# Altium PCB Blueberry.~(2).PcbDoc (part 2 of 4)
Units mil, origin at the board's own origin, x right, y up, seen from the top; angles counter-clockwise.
Board outline 2559.06 x 2204.72 mil, 6 copper layers (Top Layer, Mid-Layer 1, Mid-Layer 2, Mid-Layer 3, Mid-Layer 4, Bottom Layer); 211 components, 214 nets, 1171 pads, 598 vias.
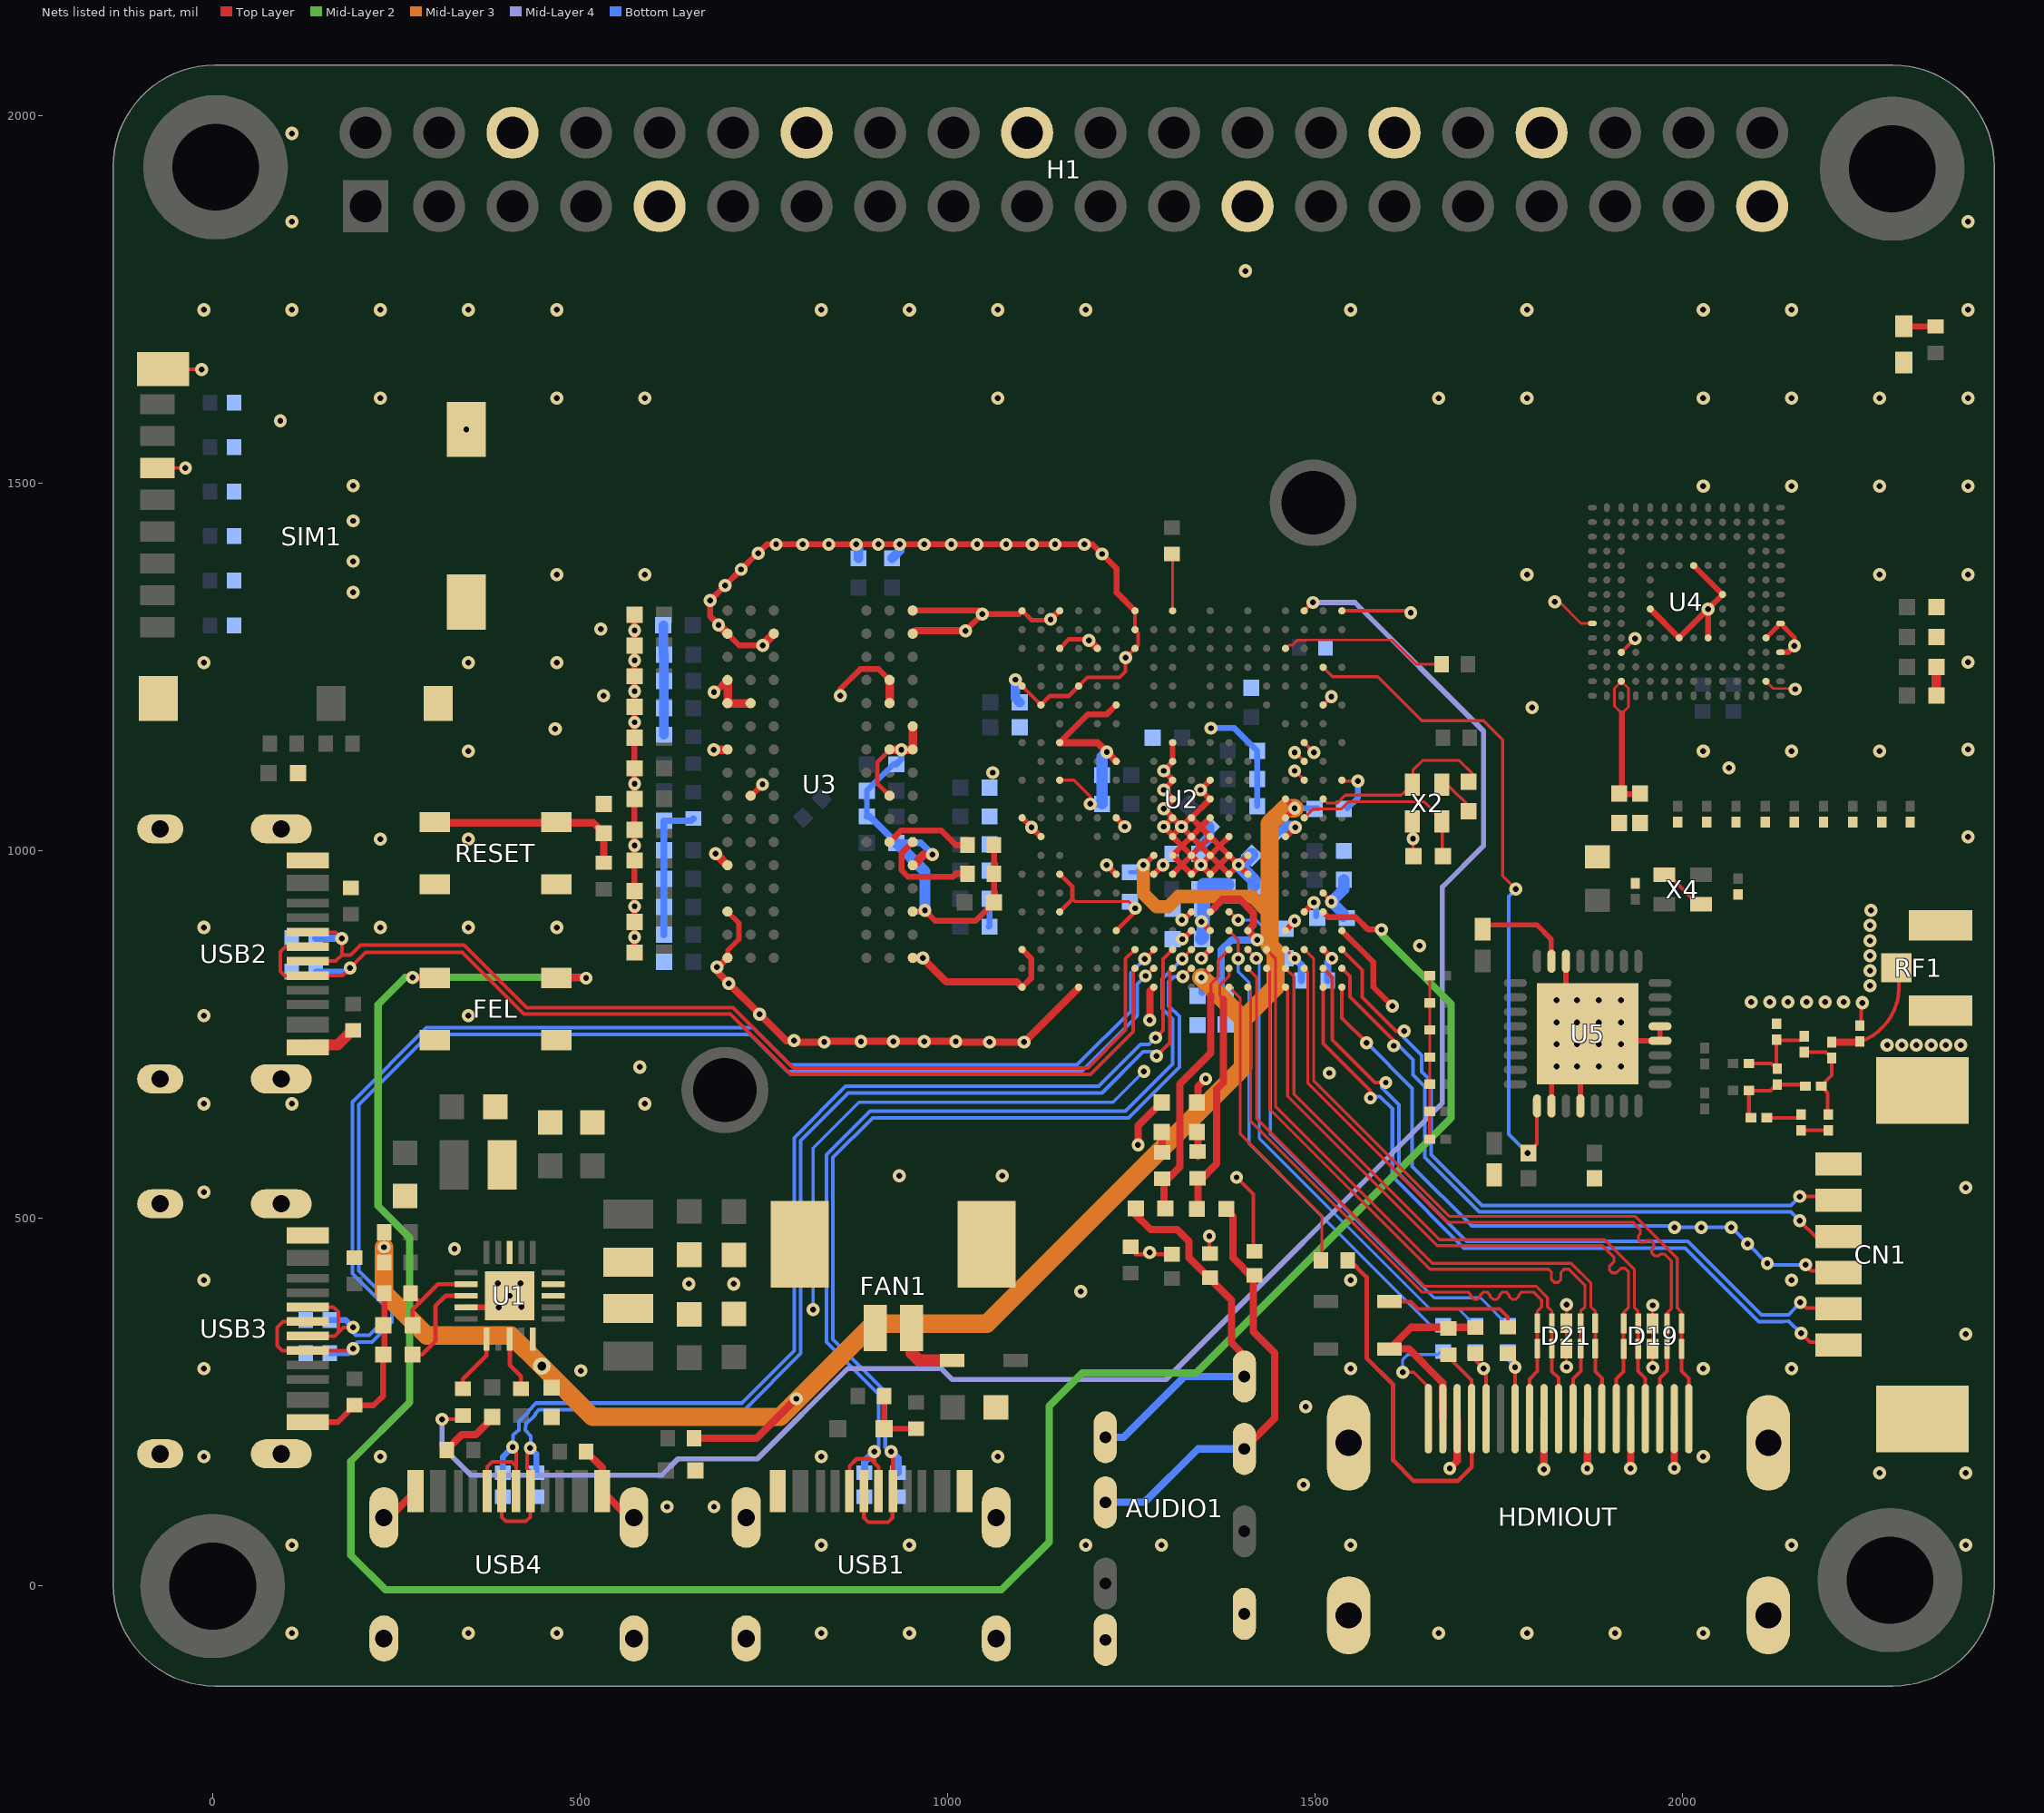
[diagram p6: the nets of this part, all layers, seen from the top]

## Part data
AUDIO1: Current Rating (Max)=500mA, JLCPCB Part Class="Extended Part", LCSC Part Name=3.5mm耳机座, Manufacturer=韩国韩荣, Voltage Rating (Max)=30V
C66 C67 C68 C69 C70 C71 C104 C105 C106 C107 C108 C117 C120: JLCPCB Part Class="Extended Part", LCSC Part Name="100nF ±10% 16V", Manufacturer=SAMSUNG(三星), Temperature Coefficient=X5R, Tolerance=±10%, Voltage Rated=16V
C87: JLCPCB Part Class="Extended Part", LCSC Part Name="100nF ±10% 25V", Manufacturer=PSA(信昌电陶), Temperature Coefficient=X7R, Tolerance=±10%, Voltage Rated=25V
C102: JLCPCB Part Class="Extended Part", LCSC Part Name="100pF ±5% 50V", Manufacturer=FH(风华), Temperature Coefficient=C0G, Tolerance=±5%, Voltage Rated=50V
C109 C123: JLCPCB Part Class="Extended Part", LCSC Part Name="7pF 25V ±0.25pF", Manufacturer=FH(风华), Temperature Coefficient=C0G, Voltage Rated=25V
C110 C113 C114 C115: JLCPCB Part Class=扩展库, LCSC Part Name="1pF 50V ±0.05pF", Manufacturer=muRata(村田), Temperature Coefficient=C0G, Voltage Rated=50V
C112 C119: JLCPCB Part Class=扩展库, LCSC Part Name="1.2pF 50V ±0.1pF", Manufacturer=FH(风华), Temperature Coefficient=C0G, Voltage Rated=50V
C116 C124: JLCPCB Part Class="Extended Part", LCSC Part Name="4.7uF ±20% 6.3V", Manufacturer=muRata(村田), Temperature Coefficient=X5R, Tolerance=±20%, Voltage Rated=6.3V
C118: JLCPCB Part Class=基础库, LCSC Part Name="10uF ±20% 6.3V", Manufacturer=SAMSUNG(三星), Temperature Coefficient=X5R, Tolerance=±20%, Voltage Rated=6.3V
C121 C122: JLCPCB Part Class="Extended Part", LCSC Part Name="22pF ±5% 50V", Manufacturer=YAGEO(国巨), Temperature Coefficient=NP0, Tolerance=±5%, Voltage Rated=50V
CN1: JLCPCB Part Class="Extended Part", Manufacturer=MOLEX
D1 D22 D23: Average Rectified Current (Io)=1A, Forward Voltage (Vf@If)=600mV@1A, JLCPCB Part Class="Extended Part", LCSC Part Name="40V 1A 600mV@1A", Manufacturer=CJ（江苏长电/长晶）, Reverse Voltage (Vr)=40V
D2 D3 D4 D5 D6 D7 D8 D9 D10 D11 D12 D13 D14 D15 D16 D17 D18: Current - Peak Pulse (10/1000μs)=-, JLCPCB Part Class="Extended Part", Manufacturer=BORN伯恩半导体, Voltage - Clamping (Max) @ Ipp=50V, Voltage - Reverse Standoff (Typ)=5V
D19 D21: JLCPCB Part Class="Extended Part", Manufacturer=SEMTECH
D20: JLCPCB Part Class="Extended Part"
FAN1: Current Rating (Max)=-, JLCPCB Part Class="Extended Part", LCSC Part Name=线至板连接器,2触点,针座,1.25mm,贴装,1排, Manufacturer=MOLEX
FEL RESET: Contact Current=50mA, JLCPCB Part Class="Extended Part", LCSC Part Name="4.2*3.2*2.5mm 立贴 轻触开关", Manufacturer=C&K, Operating Force=160gf, Operating Temperature=-40℃~+85℃, Voltage Rating (DC)=16V
H1: Color=黑色, Current Rating (Max)=-, JLCPCB Part Class="Extended Part", LCSC Part Name="2.54mm 2x20P 直插", Manufacturer=Ckmtw(灿科盟), Operating Temperature Range=-40℃~+105℃
HDMIOUT: Current Rating (Max)=500mA, JLCPCB Part Class="Extended Part", LCSC Part Name="HDMI 母 P数:19", Manufacturer=SOFNG(硕方), Operating Temperature Range=-25~+75
L1 L2 L3: DC Resistance (DCR)=264mΩ, JLCPCB On Sale=1, JLCPCB Part Class="Extended Part", LCSC Part Name="2.2uH ±20% 1.1A 264mΩ", Manufacturer=CENKER(岑科), Manufacturer Part=CKCS201610-2.2uH/M, Rated Current=1.1A, Tolerance=±20%
L4 L5: DC Resistance (DCR)=700mΩ, Frequency - Self Resonant=3.2GHz, JLCPCB Part Class=扩展库, LCSC Part Name="10nH ±3%", Manufacturer=muRata(村田), Q @ Freq=14@500MHz, Rated Current=250mA, Ratings=-, Tolerance=±3%
L6 L7 L8: DC Resistance (DCR)=200mΩ, Frequency - Self Resonant=500MHz, JLCPCB Part Class=扩展库, LCSC Part Name="2.7nH ±0.1nH", Manufacturer=Sunlord(顺络), Q @ Freq=13@500MHz, Rated Current=500mA, Ratings=-
L9: DC Resistance (DCR)=-, JLCPCB Part Class=扩展库, LCSC Part Name="4.7uH ±20%", Manufacturer=TDK, Tolerance=±20%
LED1: Color Temperature=6000K~7000K, Emitted Color=红灯, Forward Current=25mA, JLCPCB Part Class="Extended Part", LCSC Part Name="红灯 正贴 色温6000K~7000K", Lens Color=无色透明, Manufacturer=XINGLIGHT(成兴光), Operating Temperature=-30℃~+85℃, Power Dissipation=55mW
R28: JLCPCB Part Class="Extended Part", LCSC Part Name="10kΩ ±0.5%", Manufacturer="EVER OHMS(天二科技)", Operating Temperature Range=-55~+155, Overload Voltage (Max)=25V, Power(Watts)=63mW, Temperature Coefficient=±25ppm/, Tolerance=±0.5%
R53: JLCPCB Part Class="Basic Part", LCSC Part Name="1MΩ ±1% 100mW", Manufacturer=UNI-ROYAL(厚声), Operating Temperature Range=-55℃~+155℃, Overload Voltage (Max)=75V, Power(Watts)=100mW, Temperature Coefficient=±100ppm/℃, Tolerance=±1%
R54: JLCPCB Part Class="Extended Part", LCSC Part Name="100kΩ ±1% 62.5mW", Manufacturer=YAGEO(国巨), Operating Temperature Range=-55℃~+155℃, Overload Voltage (Max)=50V, Power(Watts)=62.5mW, Temperature Coefficient=±100ppm/℃, Tolerance=±1%
R56: JLCPCB Part Class="Extended Part", LCSC Part Name="10kΩ ±1% 62.5mW", Manufacturer=YAGEO(国巨), Operating Temperature Range=-55℃~+155℃, Overload Voltage (Max)=50V, Power(Watts)=62.5mW, Temperature Coefficient=±100ppm/℃, Tolerance=±1%
RF1: Frequency-Max=6GHz, JLCPCB Part Class=ExtendedPart, LCSC Part Name=IPEX内针IPEX内针天线座IPEX-1IPEX11代, Manufacturer=BATWIRELESS(蝙蝠无线), Operating Temperature Range=-
SIM1: JLCPCB Part Class="Extended Part", LCSC Part Name="拔插式 MicroSD卡(TF卡) 卡座", Manufacturer=MOLEX, Operating Temperature Range=-
U3: JLCPCB Part Class="Extended Part", Manufacturer=HYNIX(海力士)
U4: Manufacturer=Kingston(金士顿), Manufacturer Part=EMMC04G-M627-A01
U5: JLCPCB Part Class=扩展库, Manufacturer=REALTEK(瑞昱)
USB1 USB2 USB3 USB4: JLCPCB Part Class="Extended Part", Manufacturer=XUNPU
X2 X4: library part SX32Y024000BC1T, Frequency Stability=-, JLCPCB Part Class="Extended Part", LCSC Part Name="3225 24M 12PF  10ppm  -20 -75", Manufacturer=TKD(泰晶)

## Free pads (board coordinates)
  round 196.85 hole 118.11: 1(0,0) 1(4,1930) 1(2282,8) 1(2285,1928)
  round 118.11 hole 86.61: 1(696.94,674.81) 1(1497.12,1473.59)

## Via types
v1: diameter 17.7, hole 7.9, Top Layer to Bottom Layer, 439 vias
v2: diameter 18, hole 8, Top Layer to Bottom Layer, 138 vias
v3: diameter 24, hole 15, Top Layer to Bottom Layer, 19 vias
v4: diameter 24, hole 12, Top Layer to Bottom Layer, 2 vias

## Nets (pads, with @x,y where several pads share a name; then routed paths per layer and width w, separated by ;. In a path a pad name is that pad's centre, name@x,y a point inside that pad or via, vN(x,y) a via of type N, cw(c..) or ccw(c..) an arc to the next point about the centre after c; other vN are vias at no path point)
1V8: C1.2 C14.2 C15.2 C16.2 C98.1 R2.1 R3.1 R49.2 U1.15 U2.D11 U2.D12 U2.F18 U2.H17 U2.H20 U2.L14 | length 2795.3
  Top Layer w8: R3.1@233.44,440.28 233,440.72 v1(233,461) 233,480.84 R2.1@233.44,481.28 ; v1(1266,981) 1267.47,981 U2.L14@1280.38,993.91 ; v1(1345,828) 1345,828.21 U2.H20@1357.16,840.37 ; U2.D12@1459.52,1045.09 1472,1057.57 v1(1472,1058) 1472,1058.19 U2.D11@1459.52,1070.68
  Top Layer w10: R49.2@655,201 740,201 v1(793.88,254.88) ; U2.H17@1357.16,917.14 1374.02,934 1398,934 1416,916 1416,899.21 U2.F18@1408.34,891.55 1420.88,879 v1(1421,879)
  Mid-Layer 3 w18: v1(1266,981) 1266,942 1284,924 1300,924 1314,938 1414.47,938 1438,914.47
  Mid-Layer 3 w25: v1(233,461) 233,399 291,341 406,341 v4(447.72,299.28) 517,230 772,230 899,357 1053.14,357 1402,705.86 1402,771 ; v1(1345,828) 1402,771 ; v1(1472,1058) 1459,1058 1438,1037 1438,914.47 1438,871.14 1446,863.14 1446,815 1402,771
  Bottom Layer w5: C16.2@1248,971.01 1256.01,971.01 v1(1266,981)
  Bottom Layer w8: v1(1472,1058) C98.1@1504.01,1058
  Bottom Layer w10: v1(1345,828) 1346,827 C15.2@1346,808.01 ; C14.2@1378,804.01 1372,810.01 1372,865 1386,879 v1(1421,879)
AGND: C92.1 C93.1 R31.1 R32.2 U2.H18 | length 129.9
  Top Layer w8: v1(1345,904) 1357.16,891.84 U2.H18@1357.16,891.55
  Bottom Layer w8: C92.1@1345,880.99 C92.1@1346.99,879
  Bottom Layer w18: C92.1@1345,880.99 1346.99,882.99 C93.1@1348.21,919 ; C93.1@1348.21,916.09 C93.1@1348.21,919 ; R32.2@1381,954 1348.21,954 C93.1@1348.21,919
ANT: C115.2 L8.1 RF1.1 | length 164.1
  Top Layer w5: C115.2@2240.43,740.17 ccw(c2215.29,814.92) RF1.1@2289.71,841
  Top Layer w10: L8.1@2202.65,739.85 2240.11,739.85 C115.2@2240.43,740.17 ; C115.2@2240,740 ccw(c2209.51,817.73) C115.2@2240.43,740.17 ; C115.2@2241,740.74 C115.2@2240.43,740.17
AP_REG_ON: U2.C9 | length 18.1
  Top Layer w4.5: v1(1472,1134) 1472.96,1134 U2.C9@1485.11,1121.86
BT_RSTN: U2.C10 | length 18.4
  Top Layer w4: v1(1472,1109) 1472.37,1109 U2.C10@1485.11,1096.27
CS: R54.1 U2.B4 U5.25 | length 938.8
  Top Layer w4: U2.B4@1510.7,1249.81 1523.5,1237 1585,1237 1645,1177 1729,1177 1755,1151 1755,966 v1(1773,948)
  Top Layer w5: v1(1789,589) 1801.76,601.76 U5.25@1801.76,653.11
  Bottom Layer w5: v1(1773,948) 1763.25,938.25 1763.25,614.75 v1(1789,589)
D0_N: D9.1 U2.J19 USB1.A7 USB1.B7 | length 1300.2
  Top Layer w5: v1(1319,853) 1331.57,865.57 U2.J19@1331.57,865.96
  Top Layer w5.4: USB1.B7@866.5,129.3 866.5,163.5 876,173 895,173 900,168 ; v1(900,183) 900,168 ; USB1.A7@905.8,129.3 906,129.5 906,162 900,168
  Bottom Layer w5: v1(900,183) 906,189 906,261 835,332 835,586.73 894.27,646 1242,646 1306,710 1306,771.27 1291.64,785.64 1291.64,825.64 v1(1319,853)
  Bottom Layer w10: D9.1@886.86,154.37 886.86,169.86 v1(900,183)
D0_P: D11.1 U2.J20 USB1.A6 USB1.B6 | length 1319.9
  Top Layer w5: v1(923,183) 925.5,180.5 USB1.B6@925.5,129.3 ; v1(1320,829) 1320.2,829 U2.J20@1331.57,840.37
  Top Layer w5.4: USB1.A6@886.2,129.3 886.2,92.8 892,87 919,87 925,93 925,128.8 USB1.B6@925.5,129.3
  Bottom Layer w5: v1(923,183) 921,183 915,189 915,264.73 844,335.73 844,583 898,637 1246,637 1315,706 1315,775 1300.64,789.36 1300.64,821.91 1307.19,828.47 v1(1320,829)
  Bottom Layer w10: v1(923,183) 932.23,173.77 D11.1@932.23,154.37
D1_N: D13.1 U2.M19 USB2.A7 USB2.B7 | length 1434.8
  Top Layer w5: USB2.A7@129.3,850.2 167.32,850.2 175.76,858.64 ; USB2.B7@129.3,889.5 167.32,889.5 v1(175.76,881.06) 175.76,858.64 ; U2.M19@1254.79,865.96 1242,853.17 1242,756.73 1190.27,705 790,705 708,787 427,787 342,872 201,872 187.64,858.64 175.76,858.64
  Bottom Layer w10: D13.1@140.39,881.47 175.35,881.47 v1(175.76,881.06)
D1_P: D14.1 U2.M20 USB2.A6 USB2.B6 | length 1471.8
  Top Layer w5: USB2.A6@129.3,869.8 98.8,869.8 92,863 92,836 98,830 128.8,830 USB2.B6@129.3,830.5 176.5,830.5 v1(187,841) 208,862 339.27,862 423.27,778 704.27,778 786.27,696 1194,696 1252,754 1252,837.58 U2.M20@1254.79,840.37
  Bottom Layer w8: D14.1@140.39,836.1 182.1,836.1 v1(187,841)
D2_N: D17.1 U2.L19 USB3.A7 USB3.B7 | length 1799.8
  Top Layer w5: USB3.A7@129.3,340.2 129.5,340 166,340 171,345 ; USB3.B7@129.3,379.5 164.5,379.5 171,373 171,345 ; v1(191,352) 178,352 171,345 ; v1(1268,853) 1280.38,865.38 U2.L19@1280.38,865.96
  Bottom Layer w5: v1(191,352) 191,344.75 194.75,341 213,341 234.64,362.64 234.64,380.64 190,425.27 190,658.73 290.91,759.64 735.36,759.64 786,709 1176,709 1249,782 1249,834 v1(1268,853)
  Bottom Layer w8: D17.1@159.39,361.99 181.01,361.99 v1(191,352)
D2_P: D18.1 U2.L20 USB3.A6 USB3.B6 | length 1819.5
  Top Layer w5: USB3.A6@129.3,359.8 95.8,359.8 88,352 88,327 94.5,320.5 USB3.B6@129.3,320.5 188.5,320.5 v1(191,323) ; v1(1269,830) 1279.37,840.37 U2.L20@1280.38,840.37
  Bottom Layer w5: v1(191,323) 191,325.75 197.25,332 216.73,332 243.64,358.91 243.64,384.36 199,429 199,655 294.64,750.64 731.64,750.64 782.27,700 1182,700 1258,776 1258,819 v1(1269,830)
  Bottom Layer w8: D18.1@159.39,316.62 184.62,316.62 v1(191,323)
D3_N: D15.1 U2.K19 USB4.A7 USB4.B7 | length 1600.8
  Top Layer w5: USB4.B7@373.5,129.3 373.5,162.5 380,169 407,169 413,163 ; v1(408,189) 413,184 413,163 ; USB4.A7@412.8,129.3 413,129.5 413,163 ; v1(1283,746) 1293,756 1293,852.99 U2.K19@1305.97,865.96
  Bottom Layer w5: v1(408,189) 408.68,205.34 416.5,212.53 416.81,220.02 416.81,223.75 429.7,236.64 429.7,238.42 440.27,249 720,249 791,320 791,609.73 861.27,680 1205.27,680 1262.27,737 1274,737 v1(1283,746)
  Bottom Layer w8: D15.1@394.86,154.37 394.86,159.89 394.86,175.86 v1(408,189)
D3_P: D16.1 U2.K20 USB4.A6 USB4.B6 | length 1618.7
  Top Layer w5: USB4.A6@393.2,129.3 393.2,93.8 399,88 426,88 432,94 432,128.8 USB4.B6@432.5,129.3 432.5,155.5 428,160 428,184 v1(432,188) ; v1(1284,721) 1302,739 1302,836.4 U2.K20@1305.97,840.37
  Bottom Layer w5: v1(432,188) 432.68,204.34 425.49,212.15 425.81,219.83 425.81,220.02 438.7,232.91 438.7,234.7 444,240 723.73,240 800,316.27 800,606 865,671 1210,671 1266,727 1278,727 v1(1284,721)
  Bottom Layer w8: v1(432,188) 440.23,179.77 440.23,159.89 D16.1@440.23,154.37
EPHY_RTX: R26.1 U2.B19 | length 49.6
  Top Layer w8: U2.B19@1510.7,865.96 v1(1522.65,854) v1@1523,854
  Bottom Layer w10: R26.1@1517,824 1517,848.34 v1(1522.65,854)
EPHY_RX_N: CN1.6 U2.B21 | length 1008.8
  Top Layer w5: U2.B21@1510.7,814.77 1510.7,738.3 1575,674 v1(1575,664) ; v1(2161,344) 2173,332 2207.88,332 CN1.6@2211.88,328
  Bottom Layer w5: v1(1575,664) 1577.07,666.07 1587.93,666.07 1605,649 1605,557.27 1702.27,460 2003.27,460 2103.34,359.93 2136.5,359.93 2144.11,360.11 v1(2161,344)
EPHY_RX_P: CN1.5 U2.B20 | length 1027.6
  Top Layer w5: U2.B20@1510.7,840.37 1523,828.06 1523,743 1581,685 v1(1596,685) ; v1(2160,386) 2168,378 2215.1,378 CN1.5@2215.9,377.2
  Bottom Layer w5: v1(1596,685) 1590.75,679.75 1590.75,678.25 1614,655 1614,561 1706,469 2007,469 2107.07,368.93 2136.39,368.93 2143.89,369.11 v1(2160,386)
EPHY_TX_N: CN1.3 U2.A20 | length 915.9
  Top Layer w5: U2.A20@1536.29,840.37 1547.29,829.37 1547.29,801.71 1607,742 v1(1607,735) ; v1(2159,497) 2181,475 2211.28,475 CN1.3@2211.88,475.6
  Bottom Layer w5: v1(1607,735) 1614,735 1633,716 1633,695.31 1649,679.31 1649,583.27 1723.27,509 2147,509 v1(2159,497)
EPHY_TX_P: CN1.2 U2.A19 | length 930.8
  Top Layer w5: U2.A19@1536.29,865.96 1564,838.24 1564,801 1610,755 v1(1621,755) ; v1(2159,530) 2213.1,530 2215.9,527.2 CN1.2@2215.9,524.8
  Bottom Layer w5: v1(1621,755) 1621,746 1645,722 1645,700 1658,687 1658,587 1727,518 2147,518 v1(2159,530)
FEL: FEL.1 FEL.2 U2.B17 | length 3453.7
  Top Layer w8: U2.B17@1510.7,917.14 1517.83,910 1555,910 1572,893 v1(1590,893)
  Top Layer w10: v1(272,828) 306.6,828 305.9,827.3 FEL.1@302.32,827.32 ; FEL.2@467.68,827.32 507.7,827.3 v1(508,827)
  Mid-Layer 2 w10: v1(508,827) 507,828 v1(272,828) 262,828 225,791 225,517 268,474 268,250 188,170 188,42 235,-5 1073,-5 1138,60 1138,245 1183,290 1338,290 1685,637 1685,792 1590,887 v1(1590,893)
GND: AUDIO1.1 AUDIO1.8 C1.1 C2.2 C3.1 C4.2 C5.1 C6.2 C7.2 C8.2 C9.2 C10.2 C11.2 C12.1 C13.2 C14.1 C15.1 C16.1 C17.1 C18.1 C19.1 C20.1 C21.1 C22.1 C23.1 C24.1 C25.1 C26.1 C27.1 C28.1 C29.1 C30.1 C31.1 C32.1 C33.1 C34.1 C35.1 C36.1 C37.1 C38.1 C39.1 C40.1 C41.1 C42.1 C43.1 C44.1 C45.1 C46.1 C47.1 C48.1 C49.1 C50.1 C51.1 C52.1 C53.1 C54.1 C55.1 C56.1 C57.1 C58.1 C59.1 C60.1 C61.1 C62.1 C63.1 C64.1 C65.1 C66.2 C67.2 C68.1 C69.1 C70.1 C71.1 C75.1 C76.1 C77.1 C81.1 C82.1 C83.1 C87.2 C88.1 C90.1 C94.2 C95.1 C96.1 C97.2 C98.2 C99.2 C100.1 C102.1 C104.2 C105.2 C106.2 C107.1 C108.2 C114.1 C115.1 C116.1 C117.1 C118.1 C119.2 C120.2 C121.2 C122.2 C124.2 CN1.1 CN1.4 CN1.7 CN1.8 D2.1 D3.1 D4.1 D5.1 D6.1 D7.1 D8.1 D9.2 D10.1 D11.2 D12.1 D13.2 D14.2 D15.2 D16.2 D17.2 D18.2 D19.3 D19.8 D21.3 D21.8 FAN1.2 FAN1.3 FAN1.4 FEL.3 FEL.4 H1.6 H1.9 H1.14 H1.20 H1.25 H1.30 H1.34 H1.39 HDMIOUT.2 HDMIOUT.5 HDMIOUT.8 HDMIOUT.11 HDMIOUT.17 HDMIOUT.20 HDMIOUT.21 HDMIOUT.22 HDMIOUT.23 L6.1 LED1.2 R1.1 R6.2 R8.1 R9.1 R11.1 R26.2 R30.1 R32.1 R35.1 R36.2 R40.1 R43.2 R44.1 R46.2 R52.2 R53.1 R56.2 RESET.3 RESET.4 RF1.2 RF1.3 SIM1.6 SIM1.9 SIM1.10 SIM1.12 SIM1.13 SIM1.14 U1.9 U1.21 U2.A1 U2.A10 U2.A18 U2.A21 U2.B6 U2.B16 U2.D19 U2.F14 U2.F15 U2.G13 U2.G14 U2.G15 U2.H10 U2.H11 U2.H12 U2.H13 U2.H14 U2.H15 U2.H19 U2.J12 U2.J13 U2.J14 U2.J15 U2.K8 U2.K9 U2.K10 U2.K11 U2.K12 U2.K13 U2.K14 U2.K15 U2.L21 U2.M1 U2.M2 U2.M3 U2.N6 U2.N9 U2.N12 U2.N15 U2.N18 U2.P3 U2.R5 U2.R21 U2.T1 U2.T3 U2.T8 U2.T10 U2.T15 U2.T17 U2.U6 U2.U13 U2.V1 U2.V5 U2.V12 U2.V19 U2.V21 U3.A9 U3.B1 U3.B3 U3.B9 U3.D1 U3.D8 U3.E1 U3.E2 U3.E8 U3.F9 U3.G1 U3.G8 U3.G9 U3.J2 U3.J8 U3.M1 U3.M9 U3.P1 U3.P9 U3.T1 U3.T9 U4.A6 U4.C4 U4.E7 U4.G5 U4.H10 U4.J5 U4.K8 U4.N2 U4.N5 U4.P4 U4.P6 U5.4 U5.5 U5.14 U5.26 U5.28 U5.33 USB1.12 USB1.13 USB1.14 USB1.15 USB1.A1B12 USB1.B1A12 USB2.12 USB2.13 USB2.14 USB2.15 USB2.A1B12 USB2.B1A12 USB3.12 USB3.13 USB3.14 USB3.15 USB3.A1B12 USB3.B1A12 USB4.12 USB4.13 USB4.14 USB4.15 USB4.A1B12 USB4.B1A12 X2.2 X2.4 X4.2 X4.4 | length 11353.8
  Top Layer w3.5: v1(1826,1339) 1832,1339 1861.52,1309.47 U4.A6@1877.05,1309.47 ; U4.N2@2113.27,1230.74 2123,1221 2152,1221 v1(2153,1220)
  Top Layer w4: SIM1.6@-75.14,1521.01 v1(-37.01,1521.01) ; U2.T10@1152.43,1096.27 1171.73,1096.27 1194,1074 v1(1194,1064) ; 1169.77,934.52 1172.93,931.35 1245.65,931.35 v1(1255,922) ; U2.D19@1459.52,865.96 1460.04,865.96 v1(1472,854) ; U2.A10@1536.29,1096.27 1537.55,1095 v1(1558,1095) v1@1557,1096 ; C99.2@1633,996.01 v1(1633,1016.82) X2.2@1633,1042 ; C66.2@1655.85,645.8 C105.2@1655.85,682.7 C67.2@1655.85,719.6 C106.2@1655.85,756.5 C120.2@1655.85,793.4 C102.1@1655.85,830.31 ; X2.4@1673,1092 1677.99,1092 C94.2@1714,1055.99 ; v1(1842,298) 1841.6,298.4 D21.8@1841.6,323 D21.3@1841.6,357.6 1842,358 v1(1842,383) ; U5.33@1856.06,736.94 1860.81,741.68 U5.33@1870.66,751.53 ; v1(1959,297) D19.8@1959,322.7 D19.3@1959,357.3 v1(1959,382)
  Top Layer w5: SIM1.9@-67.26,1655.26 -15.26,1655.26 v1(-15,1655) ; v1(1092,1233) 1092.46,1233 U2.V5@1101.25,1224.22 U2.U6@1126.84,1198.63 ; U2.R5@1178.02,1224.22 1189.8,1236 1234,1236 1242,1244 v1(1242,1263) 1242.39,1263 U2.M3@1254.79,1275.4 1259,1279.61 1259,1296.77 U2.M2@1254.79,1300.99 U2.M1@1254.79,1326.59 ; R30.1@1252,455 1255.6,451.4 D12.1@1298,451.4 ; D8.1@1356,451.4 v1(1356,476) ; v1(1393,556) 1416,533 D10.1@1416,451.4 ; U2.B16@1510.7,942.73 1510.7,942.3 v1(1522,931) ; U2.B6@1510.7,1198.7 v1(1522,1210) ; U2.A21@1536.29,814.77 1536.29,772.71 v1(1570,739) ; U2.A1@1536.29,1326.59 1627.41,1326.59 v1(1630,1324) ; C71.1@1655.85,607.9 C66.2@1655.85,645.8 ; U4.C4@1916.41,1270.11 1935,1288.69 v1(1935,1289) ; X4.2@1975,967.54 1980.66,967.54 2020.66,927.54 X4.4@2025,927.54 ; L6.1@2114.42,637 2156,637 2160,641 C114.1@2160,641.62 ; v1(2167,437) 2175,429 2214.48,429 CN1.4@2211.88,426.4 ; C115.1@2241,762.34 2242.65,763.99 2242.65,791.93 v2(2244.31,793.58)
  Top Layer w6: U3.J8@920.87,1075.08 904,1091.94 904,1120.52 U3.G8@921.19,1137.71 ; U2.V1@1101.31,1326.69 1113.99,1314 1139,1314 v1(1140,1315) ; U2.U6@1126.84,1198.63 1139.21,1211 1164.8,1211 U2.R5@1178.02,1224.22 ; U2.T3@1152.43,1275.4 1165.03,1288 1190.48,1288 v1(1192.27,1286.22) ; U2.T17@1152.49,917.24 1169.77,934.52 1169.77,951.14 U2.T15@1152.49,968.42 ; U2.N18@1229.26,891.65 1255,917.39 v1(1255,922) ; U4.N5@2113.27,1289.78 U4.P6@2132.95,1309.47 2152,1290.43 v1(2152,1279)
  Top Layer w7: U3.T1@700.72,854.24 700.72,864.72 716,880 716,901.95 U3.P1@700.72,917.23 ; U5.26@1821.44,653.11 1821.44,702.31 U5.33@1856.06,736.94 ; U5.14@1841.13,849.96 1841.13,781.06 U5.33@1870.66,751.53 1880.5,741.69 1886,741.69 U5.4@1969.08,741.69 U5.5@1969.08,761.38 ; U5.28@1860.81,653.11 U5.33@1860.81,741.68
  Top Layer w8: USB3.B1A12@129.3,223 170.01,223 R43.2@193,246 219,246 232.01,259.01 C12.1@232.01,315 233.44,316.44 R1.1@233.44,398.28 ; U1.9@345.02,379.22 388.78,379.22 v1(389,379) ; C48.1@574.01,861.77 v1(574.01,882.88) C54.1@574.01,903.54 v1(574.01,924.53) C50.1@574.01,945.31 C57.1@574.01,987.08 v1(574.01,1007.63) C56.1@574.01,1028.85 C55.1@574.01,1070.62 v1(574.01,1091.28) C49.1@574.01,1112.38 C35.1@574.01,1154.15 v1(574.01,1175.04) C42.1@574.01,1195.92 v1(574.01,1217.39) C36.1@574.01,1237.69 v1(574.01,1259.08) C43.1@574.01,1279.46 v1(574.01,1300.02) C53.1@574.01,1321.23 ; v1(688.27,1307.53) 677,1318.8 v1(677,1340.79) 677,1341 v1(697,1361) v1(719,1383) 741,1405 v1(742,1405) 754,1417 v1(766.61,1417) v1(802.51,1417) v1(838.18,1417) v1(875.4,1417) v1(905.54,1417) v1(934.79,1417) v1(968.24,1417) v1(1004.8,1417) v1(1040.03,1417) v1(1079.47,1417) v1(1115,1417) v1(1146.17,1417) v1(1186,1417) 1197,1417 v1(1210,1404) 1230,1384 1230,1351.37 U2.M1@1254.79,1326.59 ; U3.B1@700.72,1295.19 716.16,1279.75 v1(748.27,1279.75) ; U3.J2@732.21,1074.71 v1(748.03,1090.53) ; v1(854,1211) 854,1220.27 881.27,1247.53 905.85,1247.53 U3.D8@921.19,1232.19 ; U3.A9@952.37,1327.08 1042.09,1327.08 v1(1046.95,1322.22) ; U3.P9@952.68,917.23 967.23,917.23 v1(969,919) 983,905 1037.99,905 C32.1@1062.99,930 R9.1@1063,969 R8.1@1063,1008 ; v1(1024.27,1299.53) v1(1046.95,1322.22) ; U2.V21@1101.25,814.77 1114,827.52 1114,853.2 U2.V19@1101.25,865.96 ; U2.V12@1101.25,1045.09 U2.U13@1126.84,1019.5 ; U2.V1@1101.31,1326.69 1096.84,1322.22 v1(1046.95,1322.22) ; v1(1140,1315) 1151.69,1326.69 U2.T1@1152.49,1326.69 ; U2.T8@1152.43,1147.45 1190.98,1186 1216.57,1186 U2.N6@1229.2,1198.63 ; v1(1216,981) 1216.51,981 U2.N15@1229.2,968.32 ; U2.N12@1229.2,1045.09 1241,1033.28 v1(1241,1033) ; v1@1293,1109 v1(1294,1109) ; U2.K15@1305.97,968.32 1318.76,981.11 ; U2.K14@1305.97,993.91 1318.76,981.11 ; U2.K8@1305.97,1147.45 U2.K9@1305.97,1121.86 1305.97,1120.97 v1(1294,1109) ; U2.K14@1305.97,993.91 1318.77,1006.7 ; v1@1345,854 v1(1345.2,854) U2.H19@1357.16,865.96 ; U2.H12@1357.16,1045.09 1344.36,1032.29 ; U2.H10@1357.16,1096.27 1357.16,1096.16 v1(1344,1083) 1356.32,1070.68 U2.H11@1357.16,1070.68 U2.J12@1331.57,1045.09 ; U2.G13@1382.75,1019.5 1369.95,1006.7 ; U2.F15@1408.34,968.32 v1(1395.54,981.11) ; U2.F14@1408.34,993.91 v1(1395.54,981.11) ; U2.A18@1536.29,891.55 1579,848.83 1579,815 v1(1605,789) ; U4.E7@1955.78,1329.16 U4.G5@1995.15,1289.78 v1(2034.52,1329.16) ; U4.H10@2014.85,1388.22 U4.K8@2054.22,1348.84 v1(2034.52,1329.16) ; U4.J5@2034.52,1289.78 v1(2034.52,1329.16) ; U4.P4@2132.95,1270.11 2143.1,1270.11 v1(2152,1279) ; v1(1294,1109) 1305.97,1097.03 U2.K10@1305.97,1096.27 1305.97,1094.97 v1(1294,1083) 1305.97,1071.03 U2.K11@1305.97,1070.68 1305.97,1069.37 v1(1294,1057.4) 1305.97,1045.43 U2.K12@1305.97,1045.09 ; U2.K13@1305.97,1021.03 v1(1317.99,1033.06) ; U2.K13@1305.97,1021.03 v1(1294,1033) 1305.97,1044.97 U2.K12@1305.97,1045.09 ; U2.K13@1305.97,1021.03 U2.K13@1305.97,1019.5 1318.77,1006.7 ; U2.K12@1305.97,1045.09 v1(1317.99,1033.06) ; v1(1317.99,1033.06) 1330.02,1045.09 U2.J12@1331.57,1045.09 ; v1(1317.99,1033.06) U2.J13@1331.57,1019.5 ; 1318.76,981.11 U2.J15@1331.57,968.32 v1(1344.36,981.11) ; 1318.76,981.11 U2.J14@1331.57,993.91 ; 1318.77,1006.7 U2.J14@1331.57,993.91 ; 1318.77,1006.7 U2.J13@1331.57,1019.5 ; U2.J14@1331.57,993.91 1344.36,1006.7 ; U2.J14@1331.57,993.91 v1(1344.36,981.11) ; U2.J13@1331.57,1019.5 1344.36,1006.7 ; U2.J13@1331.57,1019.5 1344.36,1032.29 ; U2.J12@1331.57,1045.09 1344.36,1032.29 ; v1(1344.36,981.11) U2.H15@1357.16,968.32 1369.95,981.11 ; v1(1344.36,981.11) U2.H14@1357.16,993.91 ; 1344.36,1006.7 U2.H13@1357.16,1019.5 ; 1344.36,1006.7 U2.H14@1357.16,993.91 ; 1344.36,1032.29 U2.H13@1357.16,1019.5 ; U2.H14@1357.16,993.91 1369.95,1006.7 ; U2.H14@1357.16,993.91 1369.95,981.11 ; U2.H13@1357.16,1019.5 1369.95,1006.7 ; 1369.95,981.11 U2.G15@1382.75,968.32 v1(1395.54,981.11) ; 1369.95,981.11 U2.G14@1382.75,993.91 ; 1369.95,1006.7 U2.G14@1382.75,993.91 ; U2.G14@1382.75,993.91 v1(1395.54,981.11)
  Top Layer w9: v1(682,1216) 683.79,1216 U3.D1@700.37,1232.58 ; v1(686,842) 687.79,842 U3.T1@700.37,854.58
  Top Layer w10: USB4.12@232.9,93.3 240,93.3 USB4.A1B12@276,129.3 ; R44.1@316,183 339,206 358,206 380.44,228.44 C3.1@380.44,230.28 ; R46.2@508,183 530,161.01 USB4.B1A12@530,129.3 566,93.3 USB4.13@573.1,93.3 ; v1(686,842) 686,836 v1(702,820) v1(744,778) 780,742 v1(791,742) 793,740 v1(832,740) 833,741 v1(882,741) v1(926,741) v1(968,741) v1(1011,741) 1012,740 v1(1057,740) v1(1104,740) 1178.02,814.02 U2.R21@1178.02,814.77 ; U3.B9@952.37,1295.58 956.32,1299.53 v1(1024.27,1299.53) ; v1@965.98,854.24 998.22,822 1094.01,822 U2.V21@1101.25,814.77 ; U2.U6@1126.37,1198.63 U2.U6@1126.84,1198.63 ; U2.T8@1152.43,1147.45 1203.77,1147.45 v1(1216.45,1134.77) 1229.2,1122.02 U2.N9@1229.2,1121.86 ; v1(1192.27,1286.22) 1192.94,1286.22 U2.P3@1203.67,1275.5 ; v1(1259,600) 1259,626.28 C88.1@1294.36,661.64 ; v1(1275,770) 1275,809.39 U2.L21@1280.38,814.77 ; C90.1@1340.36,661.64 1340.36,679.36 v1(1351,690) ; v1(1683,160) 1693.18,170.18 HDMIOUT.17@1693.18,227.71 ; v1(1870,160) 1870.38,160.38 HDMIOUT.8@1870.38,227.71 ; v1(1929,160) 1929.44,160.44 HDMIOUT.5@1929.44,227.71 ; HDMIOUT.2@1988.51,227.71 v1(1988.51,160.49) v1@1989,160 ; v1(1811,159) 1811,227.4 HDMIOUT.11@1811.31,227.71 1811.31,159.31 v1(1811,159)
  Top Layer w12: v1(681.75,1137.71) U3.G1@700.72,1137.71 ; v1(684.41,996.53) U3.M1@700.72,980.23 ; v1(688.27,1307.53) 688.37,1307.53 U3.B1@700.72,1295.19 ; U3.D1@700.72,1232.19 700.72,1200.7 U3.E2@732.21,1200.7 ; v1(748.27,1279.75) U3.B3@763.71,1295.19 ; U3.G8@921.19,1137.71 v1(936.94,1137.71) 952.68,1137.71 U3.F9@952.68,1169.2 ; U3.E8@921.19,1200.7 U3.D8@921.19,1232.19 ; U3.T9@952.68,854.24 965.98,854.24 v1(966.27,854.53) ; U3.M9@952.68,980.23 967.68,995.22 v1(979.27,995.22)
  Top Layer w13: v2(1886,767) v2(1886,797) ; C75.1@2345.15,1211.58 C76.1@2345.15,1250.27 ; U1.21@389,379.81 389,411 v1(388,412) v1(419,412) ; U1.21@389,379.81 v1(389,379) 390,380 v1(420,380) 419,381 v1(419,412) ; U1.21@389,379.81 v1(404.12,394.92) 404.12,397.12 v1(419,412)
  Top Layer w15: USB2.B1A12@129.3,733 132.65,736.35 170.2,736.35 189.85,756 R36.2@191,756
  Bottom Layer w4: v1(817,376) 817,596 879,658 1225,658 v1(1267,700)
  Bottom Layer w5: v1(1570,739) 1632,677 1632,571 1713,490 1987,490 v1(1989,488) v1(2025.15,488) v1(2066,488) v1(2088.26,465.74) v1(2115,439) 2117,437 v1(2167,437)
  Bottom Layer w8: C62.1@890.01,1047 C63.1@890.01,1082 926.01,1118 C41.1@929.99,1118 ; C30.1@1055.99,897 1056.99,898 C39.1@1056.99,935 ; v1(1358,1167) 1389.99,1167 C23.1@1420.99,1136 C21.1@1420.99,1098 C22.1@1420.99,1061 ; v1(1395.54,981.11) v1@1400.11,981.11 ; C98.2@1544.01,1058 1558,1071.99 v1(1558,1095)
  Bottom Layer w9: C61.1@613.99,886 C60.1@614,1041.01 651.01,1041.01 R11.1@654,1044 ; C62.1@890.01,1047 893.99,1047 C58.1@929.99,1011 963.48,1011 v1(979.27,995.22) ; C41.1@929.99,1118 936.94,1124.94 v1(936.94,1137.71)
  Bottom Layer w10: v1(1194,1064) C18.1@1209.97,1064.01 ; v1(1472,854) 1481,845 R26.2@1481,824
  Bottom Layer w13: C46.1@612.99,1307 613.49,1306.5 613.49,1267.5 C40.1@613.99,1267 C64.1@614.01,1231 C34.1@614.01,1194 C59.1@614,1157.99 ; v1(875.4,1417) 878.58,1413.82 C44.1@878.58,1398.15 ; C51.1@924.27,1398.15 934.79,1408.67 v1(934.79,1417) ; v1(1092,1233) 1092,1207.99 C65.1@1097.99,1202
  Bottom Layer w15: C58.1@929.99,1011 969,971.99 v1(969,919) ; C18.1@1209.97,1064.01 C20.1@1209.97,1103.01 1209.97,1128.29 v1(1216.45,1134.77) ; R6.2@1344.36,1006.7 1355.14,1017.48 C24.1@1355.14,1032.86 ; C96.1@1537.99,911 1537.99,915.01 v1(1522,931) 1538.99,947.99 C26.1@1538.99,961
  Bottom Layer w18: v1(1395.54,981.11) 1417,959.66 R32.1@1417,954 ; v1@1400.11,981.11 C97.2@1413.85,994.85
  other v1: 618,108 682,108 501,293 1275,454 329,459 1519,698 1642,871 1114,1032 1061.27,1106.53 2063,1113 1795,1195 191,1351.75 191,1394 191,1449 191,1497 345.14,1573.57 92,1585
  other v2: 108,-64 348,-64 468,-64 828,-64 948,-64 1668,-64 1788,-64 1908,-64 2028,-64 108,56 828,56 948,56 1188,56 1291,56 1548,56 2148,56 2385,56 1484,138 2268,154 2385,154 -12,176 228,176 828,176 1068,176 2028,176 1487,244 -12,296 1548,296 2028,296 2148,296 2385,343 1181,401 648,411 709,411 -12,416 1548,416 2148,416 -12,536 2385,542 934,558 1074,558 -12,656 108,656 588,656 581,706 1828.59,707 1856,707 1886,707 1916,707 2278,736 2298,736 2318,736 2338,736 2358,736 2378,736 1828.59,737 1856,737 1886,737 1916,737 1828.59,767 1856,767 1916,767 -12,776 348,776 2093.07,794.37 2118.21,794.37 2143.35,794.37 2168.49,794.37 2193.62,794.37 2218.76,794.37 1828.59,797 1856,797 1916,797 2255,816.5 2255,837 2255,857.5 2255,878 -12,896 228,896 348,896 468,896 2255,899 2256,919 228,1016 348,1016 2388,1019 348,1136 2028,1136 2148,1136 2268,1136 2388,1138 466,1166 532,1211 -12,1256 348,1256 468,1256 2388,1257 528,1302 468,1376 588,1376 1788,1376 2268,1376 2388,1376 2028,1496 2148,1496 2268,1496 2388,1496 228,1616 468,1616 588,1616 1068,1616 1668,1616 1788,1616 2028,1616 2148,1616 2268,1616 2388,1616 -12,1736 108,1736 228,1736 348,1736 468,1736 828,1736 948,1736 1068,1736 1188,1736 1548,1736 1788,1736 2028,1736 2148,1736 2388,1736 1405,1789 108,1856 2388,1856 108,1976
H5V: D22.1 HDMIOUT.18 R41.1 R47.1 | length 269.2
  Top Layer w10: HDMIOUT.18@1673.49,227.71 1673.49,276.51 1627.5,322.5 D22.1@1601.2,322.5 1630.7,352 R41.1@1718,352
HCEC: R38.1 U2.G17 | length 774
  Top Layer w4: U2.G17@1382.75,917.14 U2.G17@1383.86,917.14 ; U2.G17@1383.36,917.64 U2.G17@1383.86,917.14 ; v1@1394,906 v1(1395,906) U2.G17@1383.86,917.14
  Bottom Layer w4: v1(1395,906) 1419,906 1439,886 1439,615 1662,392 1724.99,392 R38.1@1763,354
HDCEC: HDMIOUT.13 R37.2 R38.2 | length 116.3
  Top Layer w5: R37.2@1762,316 1771.93,306.07 HDMIOUT.13@1771.93,227.71
  Bottom Layer w4: R38.2@1763,318 1763,306.71 v1(1771.93,297.78)
HDHPD: HDMIOUT.19 R39.2 | length 158.6
  Top Layer w4: v1(1619,291) 1634,291 1653.8,271.2 HDMIOUT.19@1653.8,227.71
  Bottom Layer w4: v1(1619,291) 1619,308 1626,315 1667,315 R39.2@1670,318
HDMI_0_N: D21.2 D21.9 HDMIOUT.9 U2.E20 | length 936.1
  Top Layer w4: U2.E20@1433.93,840.37 1438,836.29 1438,649 1656,431 1817.39,431 1821.39,427 1821.39,417 1825.39,413 1830.39,413 1834.39,417 1834.39,427 1838.39,431 1845,431 1867,409 1867,380 1861.3,374.3 D21.2@1861.3,357.6
  Top Layer w5: HDMIOUT.9@1850.69,227.71 1850.69,281.69 1861.3,292.3 D21.9@1861.3,323 D21.2@1861.3,357.6
HDMI_0_P: D21.1 D21.10 HDMIOUT.7 U2.E19 | length 937.9
  Top Layer w4: U2.E19@1433.93,865.96 1446,853.88 1446,652.31 1659.31,439 1848.31,439 1875,412.31 1875,380 1881,374 D21.1@1881,357.6
  Top Layer w5: D21.1@1881,357.6 D21.10@1881,323 1881,292 1890.07,282.93 HDMIOUT.7@1890.07,227.71
HDMI_1_N: D19.5 D19.6 HDMIOUT.6 U2.D21 | length 943
  Top Layer w4: U2.D21@1459.52,814.77 1462.5,811.78 1462.5,666.5 1666,463 1890.69,463 1906.5,447.19 1906.5,441.53 1900.31,435.34 1900.31,429.69 1903.85,426.15 1909.51,426.15 1915.69,432.34 1921.35,432.34 1926.34,427.34 1926.34,379.34 1919.6,372.6 D19.5@1919.6,357.3
  Top Layer w5: HDMIOUT.6@1909.75,227.71 1909.75,281.75 1919.6,291.6 D19.6@1919.6,322.7 D19.5@1919.6,357.3
HDMI_1_P: D19.4 D19.7 HDMIOUT.4 U2.D20 | length 947.1
  Top Layer w4: U2.D20@1459.52,840.37 1471,828.88 1471,669.31 1669.31,471 1894,471 1934.34,430.66 1934.34,378.66 1939.3,373.7 D19.4@1939.3,357.3
  Top Layer w5: D19.4@1939.3,357.3 D19.7@1939.3,322.7 1939.3,292.7 1949.13,282.87 HDMIOUT.4@1949.13,227.71
HDMI_2_N: D19.2 D19.9 HDMIOUT.3 U2.C20 | length 1000.8
  Top Layer w4: U2.C20@1485.11,840.37 1490,835.47 1490,684 1679,495 1932,495 1942.08,484.92 1942.08,479.26 1939.74,476.92 1939.74,471.26 1943.27,467.73 1948.93,467.73 1951.27,470.07 1956.93,470.07 1960.47,466.53 1960.47,460.88 1958.12,458.53 1958.12,452.88 1961.66,449.34 1967.31,449.34 1969.66,451.69 1975.31,451.69 1984.55,442.45 1984.55,377.55 1978.7,371.7 D19.2@1978.7,357.3
  Top Layer w5: HDMIOUT.3@1968.82,227.71 1968.82,282.82 1978.7,292.7 D19.9@1978.7,322.7 D19.2@1978.7,357.3
HDMI_2_P: D19.1 D19.10 HDMIOUT.1 U2.C19 | length 1003.1
  Top Layer w4: U2.C19@1485.11,865.96 1498,853.06 1498,687.31 1682.31,503 1935.31,503 1992.55,445.76 1992.55,378.45 1998.4,372.6 D19.1@1998.4,357.3
  Top Layer w5: D19.1@1998.4,357.3 D19.10@1998.4,322.7 1998.4,292.6 2008.2,282.8 HDMIOUT.1@2008.2,227.71
HDMI_C_N: D21.5 D21.6 HDMIOUT.12 U2.F21 | length 880.3
  Top Layer w4: U2.F21@1408.34,814.77 1412,811.1 1412,633 1645,400 1707.81,400 1711.81,396 1711.81,394 1715.81,390 1720.81,390 1724.81,394 1724.81,396 1728.81,400 1733.81,400 1737.81,396 1737.81,394 1741.81,390 1746.81,390 1750.81,394 1750.81,396 1754.81,400 1759.81,400 1763.81,396 1763.81,394 1767.81,390 1772.81,390 1776.81,394 1776.81,396 1780.81,400 1797,400 1808,389 1808,380 1802.2,374.2 D21.5@1802.2,357.6
  Top Layer w5: HDMIOUT.12@1791.62,227.71 1791.62,281.62 1802.2,292.2 D21.6@1802.2,323 D21.5@1802.2,357.6
HDMI_C_P: D21.4 D21.7 HDMIOUT.10 U2.F20 | length 876.8
  Top Layer w4: U2.F20@1408.34,840.37 1420,828.7 1420,636.31 1648.31,408 1800.31,408 1816,392.31 1816,380 1821.9,374.1 D21.4@1821.9,357.6
  Top Layer w5: D21.4@1821.9,357.6 D21.7@1821.9,323 1821.9,292.1 1831,283 HDMIOUT.10@1831,227.71
HDSCL: HDMIOUT.15 R41.2 R42.2 | length 121
  Top Layer w5: R41.2@1718,316 1718,307 1732.56,292.44 HDMIOUT.15@1732.56,227.71
  Bottom Layer w4: R42.2@1718,318 1718,307 v1(1729.08,295.92)
HDSDA: HDMIOUT.16 R45.2 R47.2 | length 597.6
  Top Layer w5: R47.2@1674,316 1677,316 1712.87,280.13 HDMIOUT.16@1712.87,227.71
  Top Layer w6: R45.2@1545,445 1570,420.01 1570,310 1606,274 1606,171 1634,143 1694,143 1713,162 1713,227.58 HDMIOUT.16@1712.87,227.71
HHPD: R39.1 U2.G18 | length 663.6
  Top Layer w4: U2.G18@1382.75,891.55 1395.17,879.12 v1(1395.17,853.42)
  Bottom Layer w4: v1(1395.17,853.42) 1395.17,835.83 1410,821 1410,602 1658,354 R39.1@1670,354
HSCL: R42.1 U2.F19 | length 679.9
  Top Layer w4: U2.F19@1408.34,865.66 U2.F19@1408.34,865.96 1420,854.29 v1(1420,854) U2.F19@1408.34,865.66
  Bottom Layer w4: v1(1420,854) 1424,850 1424,609 1656,377 1694.99,377 R42.1@1718,354
HSDA: R45.1 U2.G21 | length 422.1
  Top Layer w4: U2.G21@1382.75,814.77 1398,799.51 1398,615 1509,504 R45.1@1509,445
HXIN: C94.1 U2.B11 X2.1 | length 256.7
  Top Layer w4: U2.B11@1510.7,1070.68 1516.37,1065 1530,1065 1541,1076 1617,1076 1633,1092 1633,1110 1646,1123 1696,1123 1714,1105 C94.1@1714,1095.99
HXOUT: C99.1 U2.C12 X2.3 | length 253.3
  Top Layer w4: U2.C12@1485.11,1045.09 1497.02,1057 1535,1057 1545,1067 1648,1067 1673,1042 C99.1@1673,996.01
IRQ: R4.1 U2.C1 | length 2517.1
  Top Layer w5: v1(312,227) 335.16,227 R4.1@340.44,232.28 ; U2.C1@1485.11,1326.59 1496.52,1338 v1(1497,1338)
  Mid-Layer 4 w7: v1(312,227) 312,190 351,151 611,151 633,173 741,173 864,296 991,296 1006,281 1297,281 1673,657 1673,951 1729,1007 1729,1163 1554,1338 v1(1497,1338)
LL: C89.1 R27.2 U2.G19 | length 392.5
  Top Layer w4: 1358,804 1358,819 1368,829 1368,851.21 U2.G19@1382.75,865.96
  Top Layer w10: R27.2@1291.57,554 1299.72,554 1316,570.28 1316,683 1358,725 1358,804 ; C89.1@1294.36,510.65 R27.2@1294.36,548.64
LPCLK: U2.C8 | length 18.8
  Top Layer w5: U2.C8@1485.11,1147.45 1498,1134.55 v1(1498,1134)
LR: C91.1 R29.2 U2.G20 | length 351.9
  Top Layer w4: 1376.18,797.82 1370,804 1370,817 1382.75,829.75 U2.G20@1382.75,840.37
  Top Layer w10: C91.1@1340.36,510.65 1340.36,548.64 1366,574.28 1366,676 1375,685 1375,797.82
NetAUDIO1_2: AUDIO1.2 AUDIO1.5 C89.2 D8.2 | length 531.6
  Top Layer w10: C89.2@1254.36,510.65 1254.36,506.64 1276,485 1312,485 1328,469 1328,446.6 1386,388.6 1386,331 1403.5,313.5 AUDIO1.5@1403.5,285.1
  Bottom Layer w10: AUDIO1.2@1214.5,202.5 1239.5,202.5 1322.1,285.1 AUDIO1.5@1403.5,285.1
NetAUDIO1_3: AUDIO1.3 AUDIO1.6 C91.2 D10.2 | length 587.1
  Top Layer w10: C91.2@1380.37,510.65 1388,503.01 1388,446.6 1416,418.6 1416,346 1445,317 1445,228.2 AUDIO1.3@1403.5,186.7
  Bottom Layer w10: AUDIO1.6@1214.5,113.9 1267.9,113.9 1340.7,186.7 AUDIO1.3@1403.5,186.7
NetC5_2: C5.2 R1.2 U1.7 | length 125.9
  Top Layer w6: R1.2@269.44,398.28 281.86,385.86 ; C5.2@272.01,355 272.01,376.01 281.86,385.86 ; U1.7@345.02,410.62 306.62,410.62 281.86,385.86
NetC12_2: C12.2 U1.8 | length 134.2
  Top Layer w6: C12.2@272.01,315 285,315 303,333 303,381 316.92,394.92 U1.8@345.02,394.92
NetC82_2: C82.2 C83.2 U4.C2 | length 238.1
  Top Layer w3.5: 1907,1197 1917,1187 1926,1196 1926,1221.15 U4.C2@1916.41,1230.74 1907,1221.32 1907,1197
  Top Layer w8: 1917,1187 1917,1077.01 C83.2@1941.87,1077.01
NetC87_1: C87.1 R28.2 RESET.1 RESET.2 | length 276
  Top Layer w10: RESET.1@302.32,1039.32 303.3,1038.3 517.7,1038.3 C87.1@532,1024.01 R28.2@532,984
NetC88_2: C88.2 R27.1 | length 28
  Top Layer w10: C88.2@1291,617.75 1291.57,617.18 R27.1@1291.57,590
NetC90_2: C90.2 R29.1 | length 37
  Top Layer w10: R29.1@1340.36,584.65 C90.2@1340.36,621.64
NetC92_2: C92.2 U2.J18 | length 17.3
  Top Layer w8: v1(1319.01,880) 1320.02,880 U2.J18@1331.57,891.55
NetC93_2: C93.2 U2.J17 | length 17.3
  Top Layer w8: v1(1318.77,906.3) 1320.73,906.3 U2.J17@1331.57,917.14
NetC95_2: C95.2 U2.D18 | length 18.6
  Top Layer w8: U2.D18@1459.52,891.55 1472,904.03 v1(1472,905)
NetC96_2: C96.2 U2.C17 | length 38.4
  Top Layer w8: U2.C17@1485.11,917.14 v1(1498,930)
  Bottom Layer w8: v1(1498,930) 1500.99,927.01 C96.2@1500.99,911
NetC97_1: C97.1 U2.D13 | length 53.2
  Top Layer w8: U2.D13@1459.52,1019.5 1460.5,1019.5 v1(1473,1032)
  Bottom Layer w18: C97.1@1442.14,1023.14 1451,1032 v1(1473,1032)
NetC109_1: C109.1 C110.1 C119.1 L7.2 | length 118.8
  Top Layer w5: C109.1@2090.01,711 2120.45,711 2127.65,703.8 2127.65,742.2 2159.56,742.2 L7.2@2165.16,747.8
NetC110_2: C110.2 C112.1 C123.1 L6.2 | length 117.3
  Top Layer w5: L6.2@2090.01,637 C123.1@2090.01,674 2119.45,674 2127.65,682.2 2163.83,682.2 C112.1@2166.03,680
NetC112_2: C112.2 C113.2 L7.1 L8.2 | length 127.9
  Top Layer w5: L7.1@2165.16,726.2 2194.7,726.2 L8.2@2202.65,718.25 2202.65,695.02 2187.63,680 2197,670.63 2197,642.62 C113.2@2198,641.62
NetC113_1: C113.1 C114.2 | length 37
  Top Layer w5: C114.2@2160,620.02 C113.1@2197,620.02
NetD1_1: D1.1 FAN1.1 | length 92.9
  Top Layer w17: FAN1.1@950.8,350.9 950.8,317.2 961,307 D1.1@1005.8,307
NetD20_1: D20.1 R33.1 R34.2 | length 88.3
  Top Layer w7: R33.1@913.63,258.7 913.5,258.57 D20.1@913.5,214 R34.2@957,214
NetD23_1: D23.1 R37.1 | length 183.5
  Top Layer w5: D23.1@1601.2,387 1630,387 1640,377 1751,377 1762,366 R37.1@1762,352
NetL1_1: L1.1 U1.18
NetL2_1: L2.1 U1.19
NetL3_1: L3.1 U1.3
NetL9_2: L9.2 U5.15 | length 131.6
  Top Layer w7: L9.2@1727.73,899.55 1801.44,899.55 1821,880 1821,850.4 U5.15@1821.44,849.96
NetLED1_1: LED1.1 R48.1 | length 43
  Top Layer w8: LED1.1@2301,1713.53 2301.08,1713.45 R48.1@2344,1713.45
NetR4_2: R4.2 U1.11 | length 80.9
  Top Layer w6: R4.2@340.44,268.28 340.44,281.44 372.62,313.62 U1.11@372.62,335.82
NetR5_2: R5.2 U1.13 | length 73.9
  Top Layer w6: U1.13@404.12,335.82 404.12,300.88 419.44,285.56 R5.2@419.44,268.28
NetR6_1: R6.1 U2.L15 | length 17.9
  Top Layer w8: U2.L15@1280.38,968.32 v1@1293,980.94
  other v1: 1293,981
NetR8_2: R8.2 U3.L8 | length 121
  Top Layer w8: U3.L8@920.87,1012.08 936.79,1028 990.99,1028 1011,1008 R8.2@1027,1008
NetR9_2: R9.2 U3.L9 | length 139.8
  Top Layer w8: U3.L9@952.37,1012.08 937,996.71 937,974 946,965 1007,965 1011,969 R9.2@1027,969
NetR12_2: R12.2 U2.D3 | length 231
  Top Layer w3.5: U2.D3@1459.52,1275.4 1464.12,1280 1469,1280 1476,1287 1604,1287 1637,1254 R12.2@1672,1254
NetR13_2: R13.2 U2.K1 | length 77.8
  Top Layer w4: R13.2@1305,1404 1305.97,1403.03 U2.K1@1305.97,1326.59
